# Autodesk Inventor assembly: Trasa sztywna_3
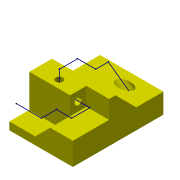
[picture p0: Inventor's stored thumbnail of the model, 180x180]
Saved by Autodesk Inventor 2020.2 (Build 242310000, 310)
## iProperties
Created: 2014-07
Part Number: Trasa sztywna_3
Document SubType Name: Assembly
Designer: F.Stasiak
Catalog Web Link: www.expertbooks.pl
Manager: www.cadconsulting.pl
Company: Fabian Stasiak CAD Consulting
Author: F.Stasiak
Subject: Zbiór ćwiczeń. Autodesk Inventor 2020. Kurs Professional
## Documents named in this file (2)
- C:\2020_Kurs_Professional\R1 Rury\Trasa sztywna_3.iam
- C:\2020_Kurs_Professional\R1 Rury\Konstrukcja_3.ipt
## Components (1 placed, 1 different names)
1. Konstrukcja_3:1
